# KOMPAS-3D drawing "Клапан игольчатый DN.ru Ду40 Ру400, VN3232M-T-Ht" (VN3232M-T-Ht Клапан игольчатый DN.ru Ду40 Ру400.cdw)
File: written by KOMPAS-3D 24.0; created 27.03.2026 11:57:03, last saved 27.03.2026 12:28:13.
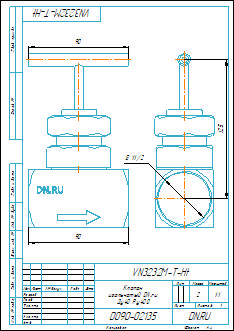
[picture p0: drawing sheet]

Document properties: Автор: Илья; Форматы листов документа: A4; Полное имя файла: VN3232M-T-Ht Клапан игольчатый DN.ru Ду40 Ру400.m3d; Масса: 2; Наименование: Клапан игольчатый DN.ru Ду40 Ру400; Количество листов документа: 1; Примечание: D090-02135

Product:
- Body: Body9  | qty 1
    Масса: 0.433192
- Body: Body7  | qty 1
    Масса: 0.81876
- Body: Body10  | qty 1
    Масса: 1.287778
- Body: Body4  | qty 1
    Масса: 2.135076
- Part/product: Клапан игольчатый DN.ru Ду40 Ру400  | designation VN3232M-T-Ht
    Масса: 2
    Раздел спецификации: Прочие изделия
    Примечание: D090-02135

Views: Вид 1, Слева, Проекционный вид 2
Referenced files in D:\Обмен\Заказы с фриланса\DN.ru\VNxxM-T-Ht Клапан игольчатый DN.ru Ду8-50 Ру400\VN3232M-T-Ht Клапан игольчатый DN.ru Ду8-50 Ру400\DN8\: VN3232M-T-Ht Клапан игольчатый DN.ru Ду8 Ру400.m3d, VN3232M-T-Ht Клапан игольчатый DN.ru Ду8 Ру400.cdw
Referenced files in D:\Обмен\Заказы с фриланса\DN.ru\VNxxM-T-Ht Клапан игольчатый DN.ru Ду8-50 Ру400\VN3232M-T-Ht Клапан игольчатый DN.ru Ду8-50 Ру400\DN40\: VN3232M-T-Ht Клапан игольчатый DN.ru Ду40 Ру400.m3d
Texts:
  VN3232M-T-Ht
  Клапан
  игольчатый DN.ru
  Ду40 Ру400
  Body4
  Клапан игольчатый DN.ru Ду40 Ру400
  VN3232M-T-Ht Клапан игольчатый DN.ru Ду40 Ру400
Dimensions and other numbers on the sheet: 0; 3; 2; 4; 90; 125; 1:1; 1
